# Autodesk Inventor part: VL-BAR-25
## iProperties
Created: 2005-08
Part Number: VL-BAR-25
Document SubType Name: Sheet Metal
Density: 1 g/cm^3
Mass: 4.22684 g
Surface Area: 81.6633 cm^2
Volume: 4.22684 cm^3
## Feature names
1. Rectangular Pattern1
2. Plate1
